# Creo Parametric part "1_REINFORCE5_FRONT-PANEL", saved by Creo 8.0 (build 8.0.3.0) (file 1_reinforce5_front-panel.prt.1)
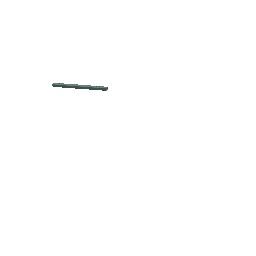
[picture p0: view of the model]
Units: millimeter Newton Second (mmNs); MM, TONNE, SECS

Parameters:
  SMT_DFLT_BEND_REL_LENGTH_TYPE = "Through All"

Other parameters: SMT_THICKNESS, SMT_PART_BEND_ALLOWANCE_FACTOR, SMT_DFLT_BEND_RADIUS, SMT_DFLT_BEND_ANGLE, SMT_DFLT_CRNR_REL_WIDTH, SMT_DFLT_CRNR_REL_DEPTH, SMT_DFLT_BEND_REL_WIDTH, SMT_DFLT_BEND_REL_DEPTH, SMT_DFLT_BEND_REL_LENGTH, SMT_DFLT_BEND_REL_ANGLE, SMT_GAP, SMT_DFLT_EDGE_TREA_WIDTH, SMT_DFLT_MITER_CUT_WIDTH, SMT_DFLT_MITER_CUT_OFFSET

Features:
  1. datum plane "DTM1"
  2. datum plane "DTM2"
  3. datum plane "DTM3"
  4. coordinate system
  5. datum plane "DTM4"
  6. protrusion
  7. round
  8. cut
  9. cut

Other named items: CS0

Layers: 0_ALL_AXIS, 0_ALL_CSYS, 0_ALL_CURVES, 0_ALL_PLANES, 0_ALL_POINTS, 0_ALL_SURFS, REINFORCE5_FRONT-PANEL

Surfaces: 24 plane, 13 cylinder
